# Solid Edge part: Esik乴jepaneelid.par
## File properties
Author: Türk
Template: iso part.par
Last saved by: Türk
Revision: 103
Application: Solid Edge
Accuracy: 0,990
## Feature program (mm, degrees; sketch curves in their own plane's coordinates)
base feature "unnamed BaseFeature 1"
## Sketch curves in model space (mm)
line (-480, -700, -125) -> (-530, -700, -125)
line (-530, -700, -125) -> (-530, -650, -125)
line (-530, -700, -125) -> (-480, -700, -125)
line (-530, -650, -125) -> (-530, -700, -125)
line (-480, -650, -125) -> (-530, -650, -125)
line (-480, -700, -125) -> (-480, -650, -125)
line (0, -675, -105) -> (0, -675, -150)
line (0, -374.4172, -150) -> (0, -425.5828, -150)
line (0, -725, -105) -> (0, -725, -150)
spline (0, -700, 200) -> (0, -786.7721, 168.5423) -> (0, -850, 125)
spline (-600, -400.2032, 353.2174) -> (-600, -400.0536, 353.3185) -> (-600, -400.0183, 352.9689)
spline (-600, -400.0183, 352.9689) -> (-600, -400.2604, 352.992) -> (-600, -400.2032, 353.2174)
closed line through (-360.1953, -400, 334.7897)
line (0, 0, 0) -> (0, 0, 193.5311)
line (-780.11, 960, -35.6207) -> (-780.0723, 960, -35.7057)
line (-647.2173, 960, -150) -> (-673.0016, 960, -150)
spline (-650, 960, 450) -> (-755.152, 960, 158.3995) -> (-650, 960, -150)
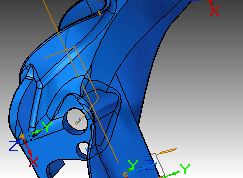
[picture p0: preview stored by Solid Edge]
